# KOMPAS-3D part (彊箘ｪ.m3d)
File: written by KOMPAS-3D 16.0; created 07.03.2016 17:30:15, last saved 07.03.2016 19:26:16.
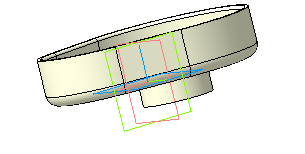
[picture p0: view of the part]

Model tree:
1. Эскиз:1
2. Операция выдавливания:1
     Расстояние 1 = 30
3. Оболочка:1
     Толщина стенки 2 = 4
4. Скругление:1
     Радиус = 7
5. Скругление:3
     Радиус = 2
6. Скругление:4
     Радиус = 4
7. Эскиз:2
8. Операция выдавливания:2
     Расстояние 1 = 15
9. Эскиз:3
10. Вырезать элемент выдавливания:1
     Расстояние 1 = 76
11. Скругление:6
     Радиус = 5
12. Скругление:7
     Радиус = 3
13. Скругление:9
     Радиус = 2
